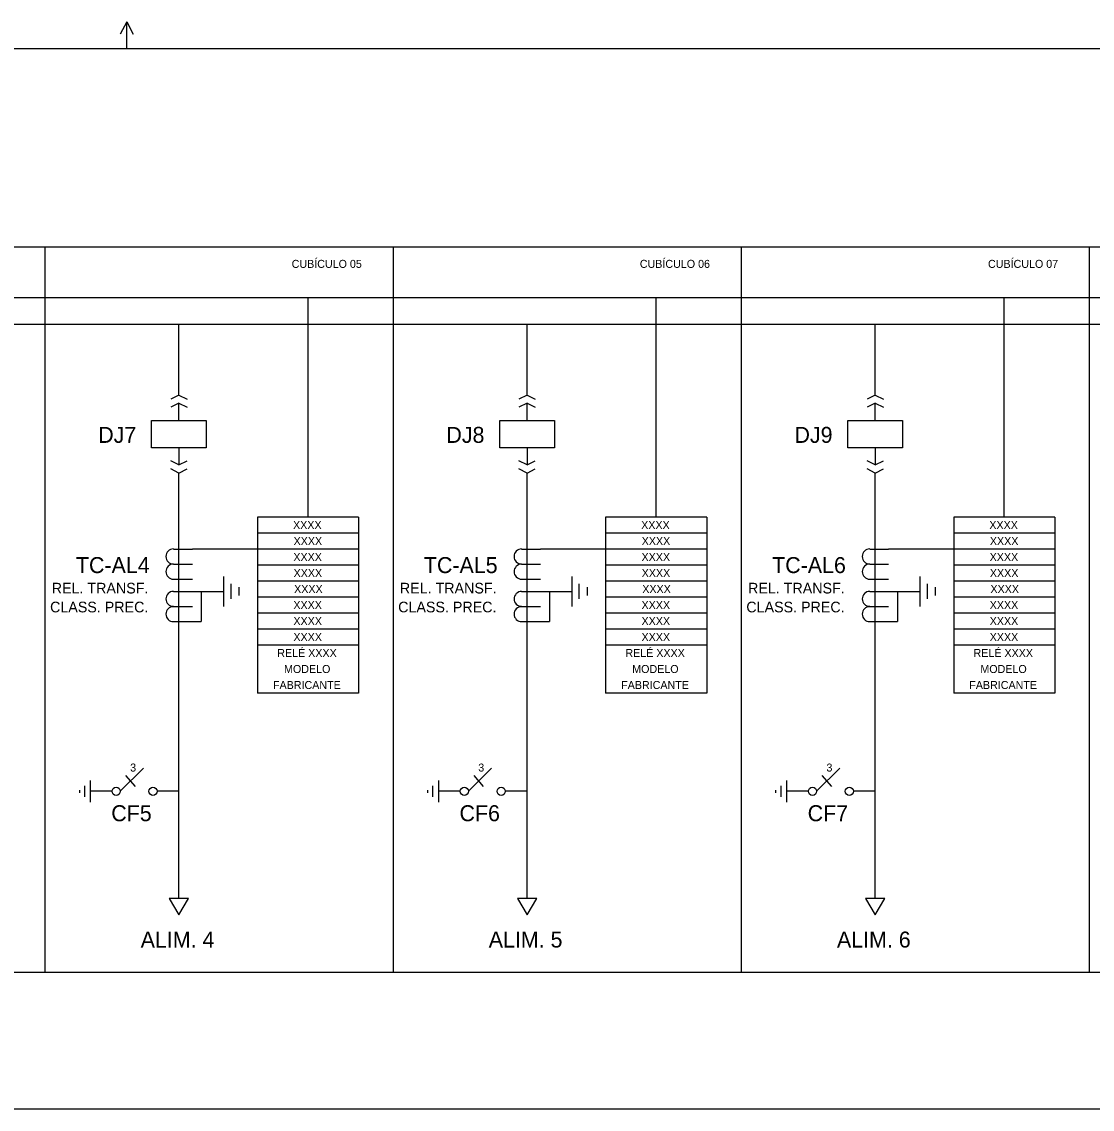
# Model space of a CAD drawing. Extents: x 563 to 1404, y 358 to 952.
# Drawn here: x 966.2 to 1166.9, y 561.3 to 765.2 of the extents above; entities that cross this region are included whole.
import ezdxf

# ---------------------------------------------------------------- set-up
doc = ezdxf.new("R2010")
doc.units = 0
doc.layers.add('13', color=7, linetype='Continuous')
doc.layers.add('New Level (0)', color=7, linetype='Continuous')

msp = doc.modelspace()

# ---------------------------------------------------------------- linework, layer by layer
for p, q in [((1296.89, 722.95), (622.37, 722.95)), ((970.5, 722.95), (970.5, 586.96)), ((970.5, 722.95), (970.5, 586.96)), ((1035.78, 722.95), (1035.78, 586.96)), ((1035.78, 722.95), (1035.78, 586.96)), ((1101.05, 722.95), (1101.05, 586.96)), ((1101.05, 722.95), (1101.05, 586.96)), ((1166.33, 722.95), (1166.33, 586.96)), ((1166.33, 722.95), (1166.33, 586.96)), ((1280.96, 713.45), (705.72, 713.45)), ((1019.85, 672.38), (1019.85, 713.45)), ((1085.12, 672.38), (1085.12, 713.45)), ((1150.4, 672.38), (1150.4, 713.45)), ((1256.75, 708.46), (681.52, 708.46)), ((995.64, 695.25), (995.64, 708.46)), ((995.64, 695.25), (995.64, 708.46)), ((1060.92, 695.25), (1060.92, 708.46)), ((1060.92, 695.25), (1060.92, 708.46)), ((1126.2, 695.25), (1126.2, 708.46)), ((1126.2, 695.25), (1126.2, 708.46)), ((995.64, 690.5), (995.64, 693.73)), ((995.64, 690.5), (995.64, 693.73)), ((1060.92, 690.5), (1060.92, 693.73)), ((1060.92, 690.5), (1060.92, 693.73)), ((1126.2, 690.5), (1126.2, 693.73)), ((1126.2, 690.5), (1126.2, 693.73)), ((990.52, 690.5), (1000.76, 690.5)), ((990.52, 685.38), (990.52, 690.5)), ((1000.76, 690.5), (1000.76, 685.38)), ((1055.8, 690.5), (1066.04, 690.5)), ((1055.8, 685.38), (1055.8, 690.5)), ((1066.04, 690.5), (1066.04, 685.38)), ((1121.08, 685.38), (1121.08, 690.5)), ((1121.08, 690.5), (1131.32, 690.5)), ((1131.32, 690.5), (1131.32, 685.38)), ((1000.76, 685.38), (990.52, 685.38)), ((995.64, 685.38), (995.64, 682.16)), ((1066.04, 685.38), (1055.8, 685.38)), ((1060.92, 685.38), (1060.92, 682.16)), ((1131.32, 685.38), (1121.08, 685.38)), ((1126.2, 685.38), (1126.2, 682.16)), ((995.64, 600.87), (995.64, 680.63)), ((1060.92, 600.87), (1060.92, 680.63)), ((1126.2, 600.87), (1126.2, 680.63)), ((1029.34, 672.38), (1010.36, 672.38)), ((1010.36, 672.38), (1010.36, 639.38)), ((1029.34, 672.38), (1029.34, 639.38)), ((1094.61, 672.38), (1075.63, 672.38)), ((1075.63, 672.38), (1075.63, 639.38)), ((1094.61, 672.38), (1094.61, 639.38)), ((1159.89, 672.38), (1140.91, 672.38)), ((1140.91, 672.38), (1140.91, 639.38)), ((1159.89, 672.38), (1159.89, 639.38)), ((1029.34, 669.38), (1010.36, 669.38)), ((1094.61, 669.38), (1075.63, 669.38)), ((1159.89, 669.38), (1140.91, 669.38)), ((994.62, 666.38), (998.16, 666.38)), ((1010.36, 666.38), (998.16, 666.38)), ((1029.34, 666.38), (1010.36, 666.38)), ((1059.9, 666.38), (1063.43, 666.38)), ((1075.63, 666.38), (1063.43, 666.38)), ((1094.61, 666.38), (1075.63, 666.38)), ((1125.17, 666.38), (1128.71, 666.38)), ((1140.91, 666.38), (1128.71, 666.38)), ((1159.89, 666.38), (1140.91, 666.38)), ((994.62, 663.55), (998.16, 663.55)), ((1029.34, 663.38), (1010.36, 663.38)), ((1059.9, 663.55), (1063.43, 663.55)), ((1094.61, 663.38), (1075.63, 663.38)), ((1125.17, 663.55), (1128.71, 663.55)), ((1159.89, 663.38), (1140.91, 663.38)), ((994.62, 660.72), (998.16, 660.72)), ((1004.02, 661.21), (1004.02, 655.63)), ((1059.9, 660.72), (1063.43, 660.72)), ((1069.3, 661.21), (1069.3, 655.63)), ((1125.17, 660.72), (1128.71, 660.72)), ((1134.58, 661.21), (1134.58, 655.63)), ((1005.42, 657.02), (1005.42, 659.82)), ((1006.9, 659.2), (1006.9, 657.64)), ((1029.34, 660.38), (1010.36, 660.38)), ((1070.7, 657.02), (1070.7, 659.82)), ((1072.18, 659.2), (1072.18, 657.64)), ((1094.61, 660.38), (1075.63, 660.38)), ((1135.97, 657.02), (1135.97, 659.82)), ((1137.45, 659.2), (1137.45, 657.64)), ((1159.89, 660.38), (1140.91, 660.38)), ((994.62, 658.42), (998.16, 658.42)), ((995.64, 658.42), (1004.02, 658.42)), ((1029.34, 657.38), (1010.36, 657.38)), ((1059.9, 658.42), (1063.43, 658.42)), ((1060.92, 658.42), (1069.3, 658.42)), ((1094.61, 657.38), (1075.63, 657.38)), ((1125.17, 658.42), (1128.71, 658.42)), ((1126.2, 658.42), (1134.58, 658.42)), ((1159.89, 657.38), (1140.91, 657.38)), ((994.62, 655.59), (998.16, 655.59)), ((1059.9, 655.59), (1063.43, 655.59)), ((1125.17, 655.59), (1128.71, 655.59)), ((994.62, 652.76), (999.83, 652.76)), ((1029.34, 654.38), (1010.36, 654.38)), ((1029.34, 654.38), (1010.36, 654.38)), ((1059.9, 652.76), (1065.11, 652.76)), ((1094.61, 654.38), (1075.63, 654.38)), ((1094.61, 654.38), (1075.63, 654.38)), ((1125.17, 652.76), (1130.39, 652.76)), ((1159.89, 654.38), (1140.91, 654.38)), ((1159.89, 654.38), (1140.91, 654.38)), ((1029.34, 651.38), (1010.36, 651.38)), ((1094.61, 651.38), (1075.63, 651.38)), ((1159.89, 651.38), (1140.91, 651.38)), ((1029.34, 648.38), (1010.36, 648.38)), ((1094.61, 648.38), (1075.63, 648.38)), ((1159.89, 648.38), (1140.91, 648.38)), ((1029.34, 639.38), (1010.36, 639.38)), ((1094.61, 639.38), (1075.63, 639.38)), ((1159.89, 639.38), (1140.91, 639.38)), ((988.98, 625.29), (984.64, 620.95)), ((1054.26, 625.29), (1049.92, 620.95)), ((1119.54, 625.29), (1115.2, 620.95)), ((977.98, 619.93), (977.98, 621.98)), ((979.01, 623), (979.01, 618.91)), ((985.63, 623.9), (987.43, 621.88)), ((1043.26, 619.93), (1043.26, 621.98)), ((1044.29, 623), (1044.29, 618.91)), ((1050.91, 623.9), (1052.71, 621.88)), ((1108.54, 619.93), (1108.54, 621.98)), ((1109.56, 623), (1109.56, 618.91)), ((1116.19, 623.9), (1117.98, 621.88)), ((976.97, 621.19), (976.97, 620.66)), ((983.1, 620.95), (979.01, 620.95)), ((995.64, 620.95), (991.55, 620.95)), ((1042.25, 621.19), (1042.25, 620.66)), ((1048.38, 620.95), (1044.29, 620.95)), ((1060.92, 620.95), (1056.82, 620.95)), ((1107.52, 621.19), (1107.52, 620.66)), ((1113.66, 620.95), (1109.56, 620.95)), ((1126.2, 620.95), (1122.1, 620.95)), ((997.45, 600.87), (993.83, 600.87)), ((993.83, 600.87), (995.64, 597.77)), ((997.45, 600.87), (993.83, 600.87)), ((995.64, 597.77), (997.45, 600.87)), ((1062.73, 600.87), (1059.11, 600.87)), ((1062.73, 600.87), (1059.11, 600.87)), ((1059.11, 600.87), (1060.92, 597.77)), ((1060.92, 597.77), (1062.73, 600.87)), ((1124.39, 600.87), (1126.2, 597.77)), ((1128.01, 600.87), (1124.39, 600.87)), ((1128.01, 600.87), (1124.39, 600.87)), ((1126.2, 597.77), (1128.01, 600.87)), ((1296.89, 586.96), (622.37, 586.96))]:
    msp.add_line(p, q)
for centre in [(983.87, 620.95), (990.78, 620.95), (1049.15, 620.95), (1056.06, 620.95), (1114.43, 620.95), (1121.33, 620.95)]:
    msp.add_circle(centre, 0.768)
for centre in [(994.62, 664.97), (1059.9, 664.97), (1125.17, 664.97), (994.62, 662.14), (1059.9, 662.14), (1125.17, 662.14), (994.62, 657.01), (1059.9, 657.01), (1125.17, 657.01), (994.62, 654.18), (1059.9, 654.18), (1125.17, 654.18)]:
    msp.add_arc(centre, 1.42, 90, 270)
at = {"layer": '13'}
for p, q in [((995.64, 695.25), (994.12, 694.49)), ((995.64, 693.73), (994.12, 692.97)), ((995.64, 695.25), (997.17, 694.49)), ((995.64, 693.73), (997.17, 692.97)), ((1060.92, 695.25), (1059.39, 694.49)), ((1060.92, 693.73), (1059.39, 692.97)), ((1060.92, 695.25), (1062.45, 694.49)), ((1060.92, 693.73), (1062.45, 692.97)), ((1126.2, 695.25), (1124.67, 694.49)), ((1126.2, 693.73), (1124.67, 692.97)), ((1126.2, 695.25), (1127.72, 694.49)), ((1126.2, 693.73), (1127.72, 692.97)), ((995.64, 682.16), (994.12, 682.92)), ((995.64, 680.63), (994.12, 681.4)), ((995.64, 682.16), (997.17, 682.92)), ((995.64, 680.63), (997.17, 681.4)), ((1060.92, 682.16), (1059.39, 682.92)), ((1060.92, 680.63), (1059.39, 681.4)), ((1060.92, 682.16), (1062.45, 682.92)), ((1060.92, 680.63), (1062.45, 681.4)), ((1126.2, 682.16), (1124.67, 682.92)), ((1126.2, 680.63), (1124.67, 681.4)), ((1126.2, 682.16), (1127.72, 682.92)), ((1126.2, 680.63), (1127.72, 681.4))]:
    msp.add_line(p, q, dxfattribs=at)
at = {"layer": 'New Level (0)'}
for p, q in [((985.85, 765.24), (984.64, 762.94)), ((985.85, 760.21), (985.85, 765.24)), ((985.85, 765.24), (987.06, 762.94)), ((999.83, 658.42), (999.83, 652.76)), ((1065.11, 658.42), (1065.11, 652.76)), ((1130.39, 658.42), (1130.39, 652.76))]:
    msp.add_line(p, q, dxfattribs=at)
msp.add_lwpolyline([(592.61, 760.21), (1379.09, 760.21), (1379.09, 561.33), (592.61, 561.33)], close=True, dxfattribs=at)

# ---------------------------------------------------------------- texts
for s, height, p in [('CUBÍCULO 05', 1.5, (1016.78, 719.09)), ('CUBÍCULO 06', 1.5, (1082.06, 719.09)), ('CUBÍCULO 07', 1.5, (1147.34, 719.09)), ('DJ7', 3, (980.51, 686.28)), ('DJ8', 3, (1045.79, 686.28)), ('DJ9', 3, (1111.06, 686.28)), ('XXXX', 1.5, (1017.04, 670.13)), ('XXXX', 1.5, (1082.31, 670.13)), ('XXXX', 1.5, (1147.59, 670.13)), ('XXXX', 1.5, (1017.14, 667.13)), ('XXXX', 1.5, (1082.41, 667.13)), ('XXXX', 1.5, (1147.69, 667.13)), ('TC-AL4', 3, (976.33, 661.86)), ('XXXX', 1.5, (1017.1, 664.13)), ('TC-AL5', 3, (1041.57, 661.86)), ('XXXX', 1.5, (1082.38, 664.13)), ('TC-AL6', 3, (1106.87, 661.86)), ('XXXX', 1.5, (1147.65, 664.13)), ('XXXX', 1.5, (1017.14, 661.13)), ('XXXX', 1.5, (1082.41, 661.13)), ('XXXX', 1.5, (1147.69, 661.13)), ('REL. TRANSF.', 2, (971.79, 658.04)), ('XXXX', 1.5, (1017.24, 658.13)), ('REL. TRANSF.', 2, (1037.07, 658.04)), ('XXXX', 1.5, (1082.52, 658.13)), ('REL. TRANSF.', 2, (1102.35, 658.04)), ('XXXX', 1.5, (1147.8, 658.13)), ('XXXX', 1.5, (1017.1, 655.13)), ('XXXX', 1.5, (1082.38, 655.13)), ('XXXX', 1.5, (1147.66, 655.13)), ('CLASS. PREC.', 2, (971.48, 654.5)), ('CLASS. PREC.', 2, (1036.75, 654.5)), ('CLASS. PREC.', 2, (1102.03, 654.5)), ('XXXX', 1.5, (1017.11, 652.13)), ('XXXX', 1.5, (1082.38, 652.13)), ('XXXX', 1.5, (1147.66, 652.13)), ('XXXX', 1.5, (1017.11, 649.13)), ('XXXX', 1.5, (1082.38, 649.13)), ('XXXX', 1.5, (1147.66, 649.13)), ('RELÉ XXXX', 1.5, (1014.08, 646.13)), ('RELÉ XXXX', 1.5, (1079.35, 646.13)), ('RELÉ XXXX', 1.5, (1144.63, 646.13)), ('MODELO', 1.5, (1015.35, 643.13)), ('MODELO', 1.5, (1080.63, 643.13)), ('MODELO', 1.5, (1145.91, 643.13)), ('FABRICANTE', 1.5, (1013.28, 640.13)), ('FABRICANTE', 1.5, (1078.56, 640.13)), ('FABRICANTE', 1.5, (1143.83, 640.13)), ('3', 1.5, (986.5, 624.65)), ('3', 1.5, (1051.77, 624.65)), ('3', 1.5, (1117.05, 624.65)), ('CF5', 3, (982.96, 615.34)), ('CF6', 3, (1048.25, 615.34)), ('CF7', 3, (1113.53, 615.34)), ('ALIM. 4', 3, (988.47, 591.64)), ('ALIM. 5', 3, (1053.73, 591.66)), ('ALIM. 6', 3, (1119.02, 591.65))]:
    msp.add_text(s, height=height).set_placement(p)

doc.saveas('drawing.dxf')
